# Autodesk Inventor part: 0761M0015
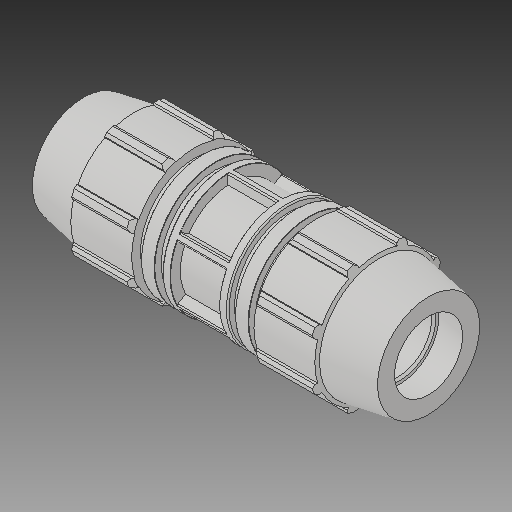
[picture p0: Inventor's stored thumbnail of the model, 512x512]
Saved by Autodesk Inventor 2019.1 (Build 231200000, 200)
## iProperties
Created: 2017-02
Part Number: 0761M0015
Material: Generic
Description: PLASSON REPAIR COUPLER 1 1/2'' - 1 1/2''
Document SubType Name: Modeling
Designer: KIM
Mass: 2544.89 g
Surface Area: 2949.22 cm^2
Volume: 2544.89 cm^3
Density: 1 g/cm^3
Appearance: Default
Author: KIM
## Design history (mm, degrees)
derived "0761M.ipt"
feature "Solid1::0761M.ipt"
tag "TaggingFeature1"
body "Solid1"
other parameters: "d1" = 243.84, "d2" = 48.1, "d4" = 20.32, "d5" = 34.83429, "d7" = 96.012, "d8" = 72.009, "d9" = 34.83429, "d11" = 9.35567, "d12" = 76.8096, "d13" = 120 deg, "d14" = 72.15, "d15" = 10 deg, "d16" = 86.4108, "d19" = 35 deg, "d20" = 17.5 deg, "d21" = 89.29116, "d23" = 0, "d25" = 360 deg, "d27" = 1.92024, "d33" = 0.2, "d34" = 4.8006, "d36" = 0, "d37" = 0.962, "d38" = 0.962, "d40" = 360 deg, "d42" = 43.8912, "d43" = 2.88036, "d46" = 1.443, "d50" = 5.308, "d51" = 76.8096, "d52" = 5.308, "d_" = 48.1, "E_" = 96.012, "H_" = 243.84, "l_" = 98.044, "d49" = 19.97166
